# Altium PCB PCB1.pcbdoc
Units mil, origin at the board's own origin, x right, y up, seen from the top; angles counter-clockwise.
Board outline 1835 x 2230 mil, 2 copper layers (Top Layer, Bottom Layer); 38 components, 28 nets, 143 pads, 62 vias.
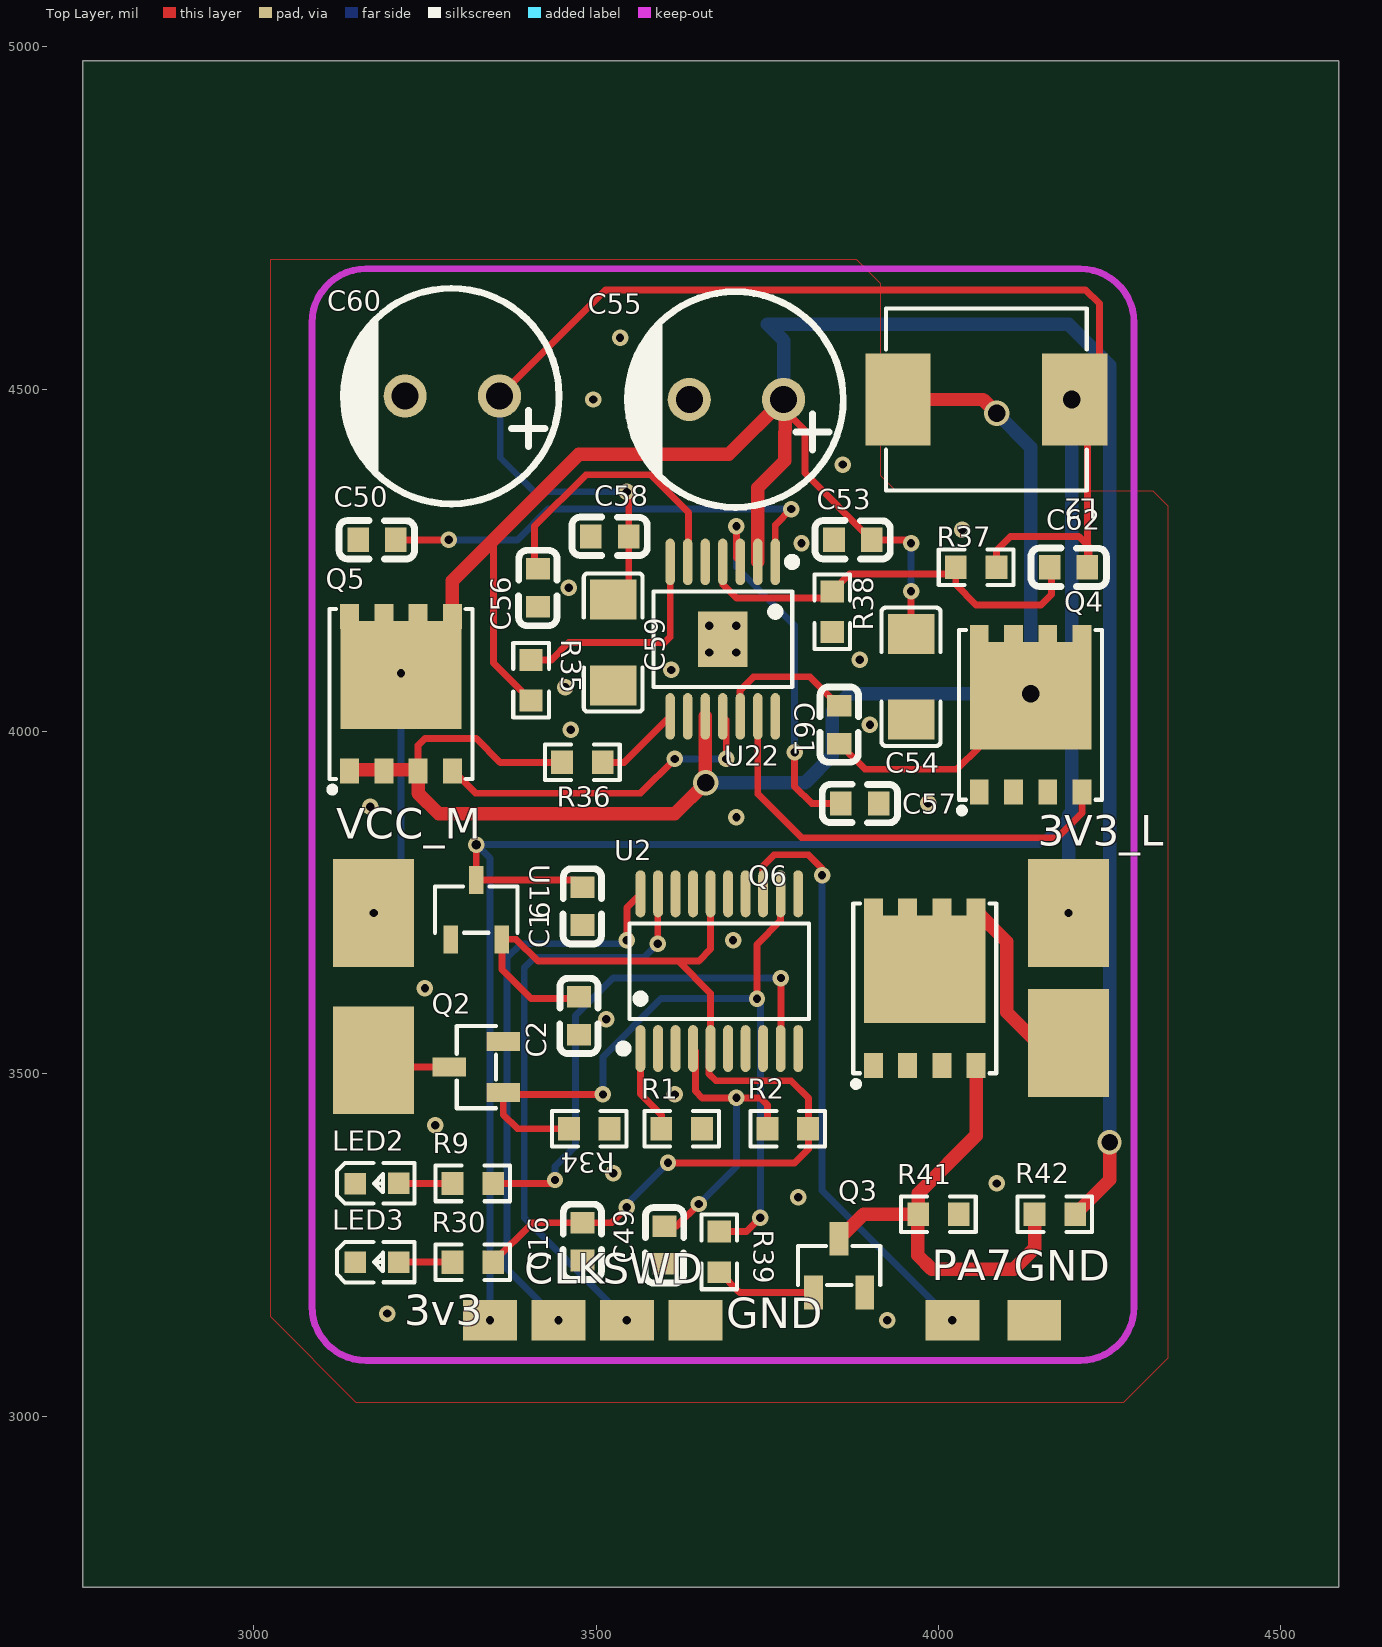
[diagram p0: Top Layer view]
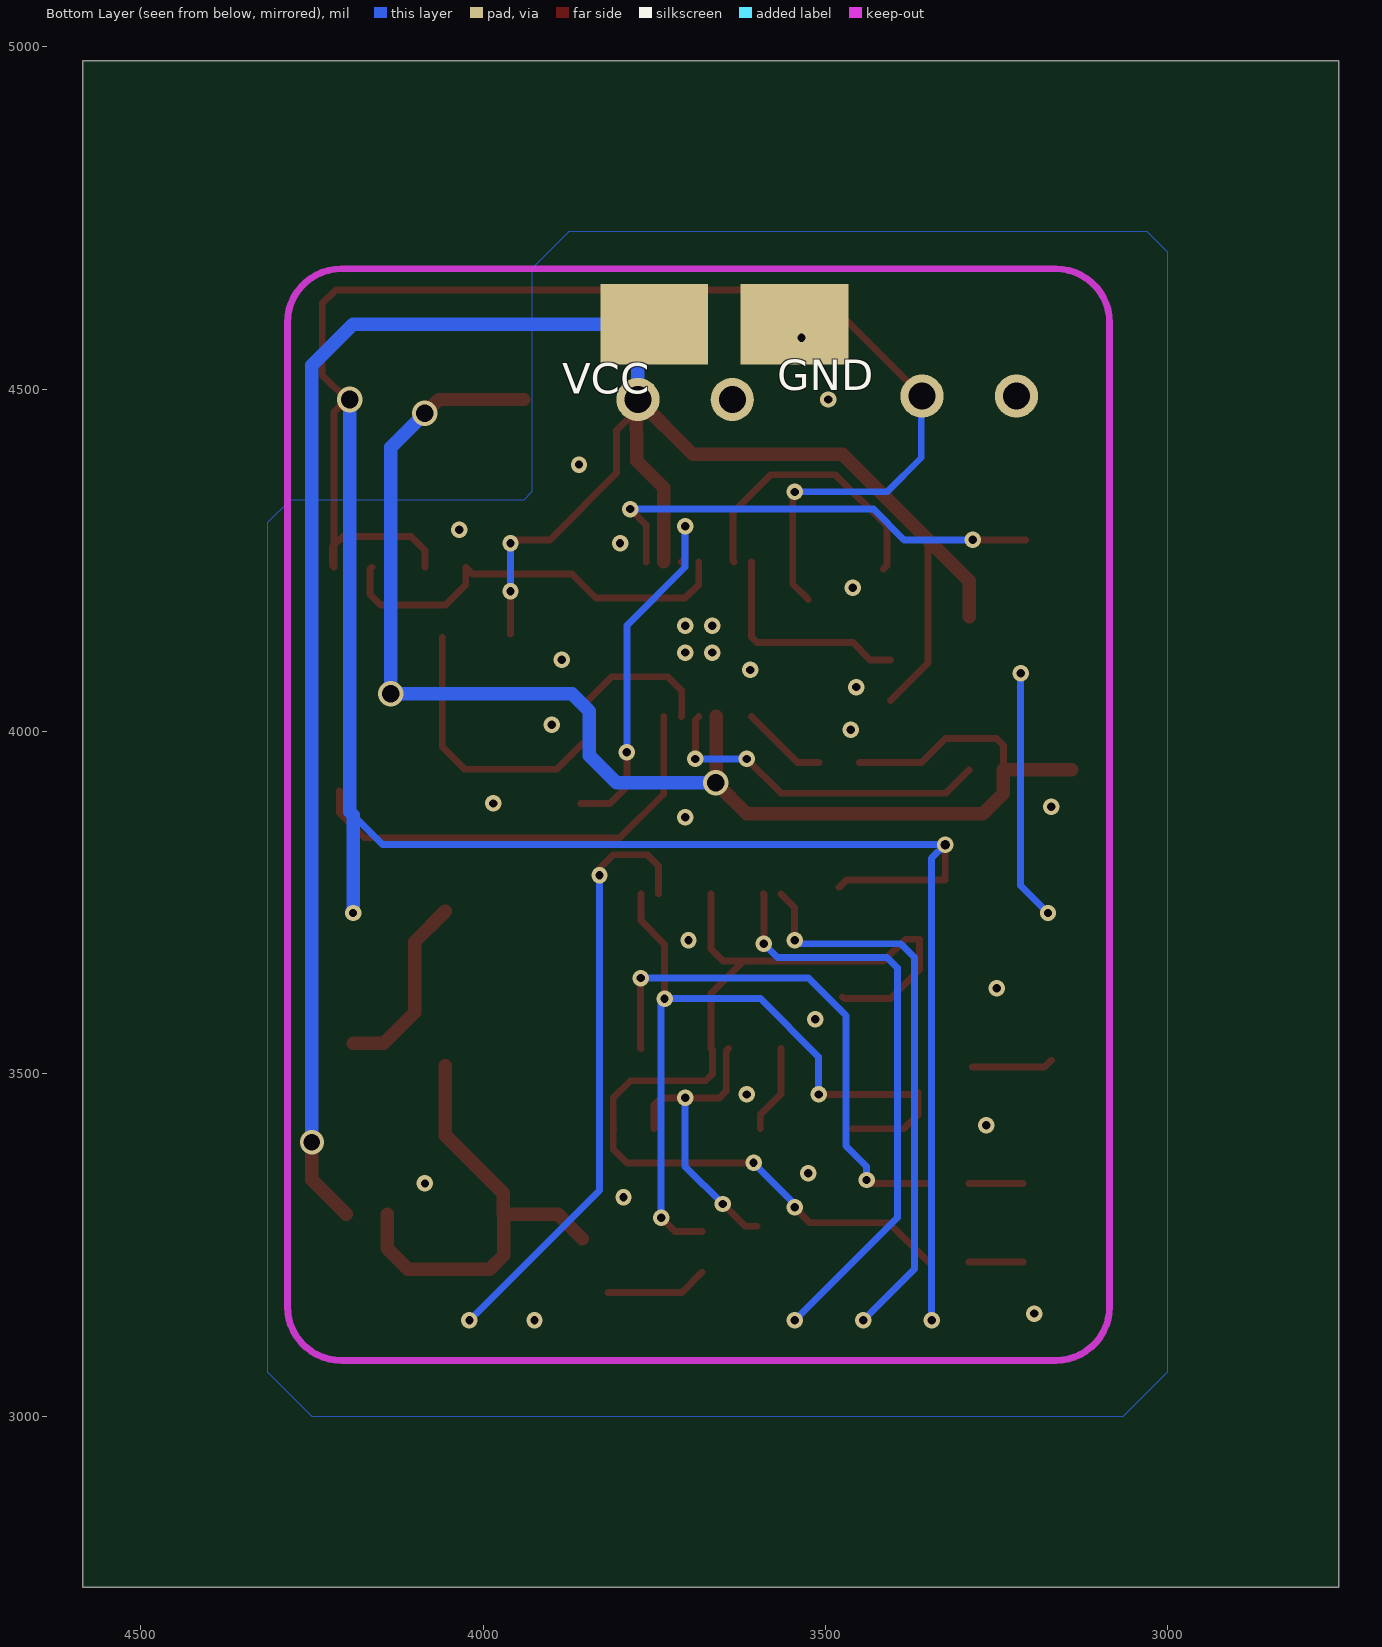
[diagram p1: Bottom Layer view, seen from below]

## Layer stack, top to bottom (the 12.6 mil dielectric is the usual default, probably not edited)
Top Layer: signal copper (thickness not stored)
Dielectric: dielectric 12.6, FR-4, Dk 4.8
Bottom Layer: signal copper (thickness not stored)

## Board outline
4585,2750 2750,2750 2750,4980 4585,4980

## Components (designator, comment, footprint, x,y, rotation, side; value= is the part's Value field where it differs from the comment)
C1 "CL10A106KP8NNNC" C0603 3480,3745 r90 top
C2 "CL10A106KP8NNNC" C0603 3475,3585 r90 top
C16 "CL10A106KP8NNNC" C0603 3480,3255 r90 top
C49 "CAP_0603" C0603 3600,3250 r90 top
C50 "CAP_0603" C0603 3180,4280 r0 top
C53 "CAP_0603" C0603 3875,4280 r0 top
C54 "CL31A106KBHNNNE" C1206 3960,4080 r90 top
C55 "KM227M035F12RR0VH2FP0" CAP-TH_BD8.0-P3.50-D0.6-FD 3705,4485 r180 top
C56 "CAP_0603" C0603 3415,4210 r90 top
C57 "CAP_0603" C0603 3885,3895 r180 top
C58 "CAP_0603" C0603 3520,4285 r0 top
C59 "CL31A106KBHNNNE" C1206 3525,4130 r90 top
C60 "KM227M035F12RR0VH2FP0" CAP-TH_BD8.0-P3.50-D0.6-FD 3290,4490 r180 top
C61 "CAP_0603" C0603 3855,4010 r270 top
C62 "CAP_0603" C0603 4190,4240 r180 top
L2 "MCS0630-100MPY1" IND-SMD_L7.3-W6.6 4070,4485 r180 top
LED2 "NCD0603R1_C84263" LED0603-RD_RED 3180,3340 r0 top
LED3 "NCD0603R1_C84263" LED0603-RD_RED 3180,3225 r0 top
Q2 "AO3400A_C347475" SOT-23-3_L2.9-W1.3-P1.90-LS2.4-BR 3325,3510 r0 top
Q3 "SS8050_C2150" SOT-23-3_L2.9-W1.3-P1.90-LS2.4-BR 3855,3220 r270 top
Q4 "BSC027N04LSG" PG-TDSON-8_L5.0-W6.0-P1.27-LS6.2-BL-EP 4134.68,4024.55 r0 top
Q5 "BSC027N04LSG" PG-TDSON-8_L5.0-W6.0-P1.27-LS6.2-BL-EP 3215,4055 r0 top
Q6 "BSC027N04LSG" PG-TDSON-8_L5.0-W6.0-P1.27-LS6.2-BL-EP 3980,3625 r0 top
R1 "0603WAF1002T5E" R0603 3625,3420 r0 top
R2 "0603WAF1002T5E" R0603 3780,3420 r0 top
R9 "0603WAF1001T5E" R0603 3320,3340 r0 top
R30 "0603WAF1001T5E" R0603 3320,3225 r0 top
R34 "Res_0603" R0603 3490,3420 r0 top
R35 "Res_0603" R0603 3405,4075 r270 top
R36 "Res_0603" R0603 3480,3955 r180 top
R37 "Res_0603" R0603 4055,4240 r0 top
R38 "Res_0603" R0603 3845,4175 r90 top
R39 "Res_0603" R0603 3680,3240 r270 top
R41 "Res_0603" R0603 4000,3295 r0 top
R42 "Res_0603" R0603 4170,3295 r0 top
U2 "STM32F030F4P6" TSSOP-20_L6.5-W4.4-P0.65-LS6.4-BL 3680,3650 r0 top
U19 "XC6206P332MR_C347376" SOT-23-3_L3.0-W1.7-P0.95-LS2.9-BR 3325,3740 r270 top
U22 "LM3150MHX/NOPB" HTSSOP-14_L5.0-W4.4-P0.65-LS6.4-BL-EP 3685,4135 r180 top

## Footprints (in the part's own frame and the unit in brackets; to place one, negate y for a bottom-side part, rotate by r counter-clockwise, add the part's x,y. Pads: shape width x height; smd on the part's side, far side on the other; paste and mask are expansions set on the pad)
C0603 [mm]
  rect 0.8x0.9 smd: 1(-0.7,0) 2(0.7,0)
  silkscreen extent -1.41,-0.71 1.39,0.72
C1206 [mm]
  rect 1.485x1.728 smd: 1(-1.593,0) 2(1.593,0)
  silkscreen extent -2.56,-1.09 2.56,1.09
CAP-TH_BD8.0-P3.50-D0.6-FD [mm]
  round 1.6 hole 1: 1(-1.75,0) 2(1.75,0)
  silkscreen extent -3.96,-4 4.04,4
HTSSOP-14_L5.0-W4.4-P0.65-LS6.4-BL-EP [mm]
  oval 0.343x1.731 smd: 1(-1.95,-2.866) 2(-1.3,-2.866) 3(-0.65,-2.866) 4(0,-2.866) 5(0.65,-2.866) 6(1.3,-2.866) 7(1.95,-2.866) 8(1.95,2.866) 9(1.3,2.866) 10(0.65,2.866) 11(0,2.866) 12(-0.65,2.866) 13(-1.3,2.866) 14(-1.95,2.866)
  rect 1.83x2.055 smd: 15(0,0)
  silkscreen extent -2.72,-3.02 2.58,1.77
IND-SMD_L7.3-W6.6 [mm]
  rect 2.424x3.42 smd: 1(3.278,0) 2(-3.278,0)
  silkscreen extent -3.73,-3.38 3.73,3.38
LED0603-RD_RED [mm]
  rect 0.8x0.8 smd: 1(-0.8,-0.003) 2(0.8,0.003)
  silkscreen extent -1.49,-0.75 1.39,0.76
PG-TDSON-8_L5.0-W6.0-P1.27-LS6.2-BL-EP [mm]
  rect 0.7x0.925 smd: 1(-1.905,-2.865) 2(-0.635,-2.865) 3(0.635,-2.865) 4(1.905,-2.865) 5(1.905,2.865) 6(0.635,2.865) 7(-0.635,2.865) 8(-1.905,2.865)
  rect 4.5x4 smd: 9(0,0.705)
  silkscreen extent -2.66,-3.66 2.65,3.15
R0603 [mil]
  rect 31.75x34.02 smd: 1(-29.66,0) 2(29.66,0)
  silkscreen extent -55,-26 55,26
SOT-23-3_L2.9-W1.3-P1.90-LS2.4-BR [mm]
  rect 1.25x0.7 smd: 1(1,-0.95) 2(1,0.95) 3(-1,0)
  silkscreen extent -0.73,-1.53 0.73,1.53
SOT-23-3_L3.0-W1.7-P0.95-LS2.9-BR [mil]
  rect 40.85x20.95 smd: 1(43.36,-37.4) 2(43.36,37.4) 3(-43.36,0)
  silkscreen extent -34,-60 34,60
TSSOP-20_L6.5-W4.4-P0.65-LS6.4-BL [mil]
  oval 14.33x68.58 smd: 1(-115.16,-113.03) 2(-89.57,-113.03) 3(-63.98,-113.03) 4(-38.39,-113.03) 5(-12.79,-113.03) 6(12.8,-113.03) 7(38.39,-113.03) 8(63.98,-113.03) 9(89.57,-113.03) 10(115.16,-113.03) 11(115.16,113.03) 12(89.57,113.03) 13(63.98,113.03) 14(38.39,113.03) 15(12.8,113.03) 16(-12.79,113.03) 17(-38.39,113.03) 18(-63.98,113.03) 19(-89.57,113.03) 20(-115.16,113.03)
  silkscreen extent -146,-119 131,70

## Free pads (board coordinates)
  rect 118.11x157.48 smd: 21(3175,3520) 21(3175,3735) 21(4190,3545) 21(4190,3735)
  rect 78.74x59.06 smd: 21(3345,3140) 21(3445,3140) 21(3545,3140) 21(3645,3140) 21(4020.79,3140) 21(4140,3140)
  rect 157.48x118.11 smd far side: 21(3545,4595) 21(3750,4595)

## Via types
v1: diameter 24.02, hole 12.2, Top Layer to Bottom Layer, 52 vias
v2: diameter 37.4, hole 25.59, Top Layer to Bottom Layer, 4 vias
v3: diameter 24, hole 12, Top Layer to Bottom Layer, 4 vias
v4: diameter 24.02, hole 13.78, Top Layer to Bottom Layer, 1 vias
v5: diameter 35.43, hole 24.02, Top Layer to Bottom Layer, 1 vias

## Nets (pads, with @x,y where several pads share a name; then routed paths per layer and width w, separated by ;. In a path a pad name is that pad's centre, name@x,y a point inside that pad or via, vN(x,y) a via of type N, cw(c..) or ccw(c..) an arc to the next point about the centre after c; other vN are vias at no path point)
3V: C2.2 C16.2 R2.2 R30.2 U2.5 U2.16 U19.2 | length 1533.1
  Top Layer w10: R30.2 3407.22,3282.56 C16.2 3522.56,3282.56 v1(3545,3305) ; C2.2 3472.44,3610 3405,3610 3362.4,3652.6 U19.2 3383.36,3696.64 3415,3665 3620,3665 ; v1(3605,3370) 3790,3370 3810,3390 3810,3419.66 R2.2 3810,3420.34 3810,3465 3785,3490 3675,3490 3665,3500 3665,3534.76 U2.5 3667.21,3617.79 3620,3665 ; U2.16 3667.21,3682.21 3650,3665 3620,3665
  Bottom Layer w10: v1(3545,3305) 3545,3310 v1(3605,3370)
3V3: C1.2 C58.2 C59.2 C60.1 C62.1 L2.2 pad.21@3345,3140 pad.21@4190,3735 R37.2 U19.3 | length 4574.9
  Top Layer w9.65: C59.2 3547.56,4215.26 C58.2 3547.56,4347.44 v1(3545,4350)
  Top Layer w10: v4(3325,3835) U19.3 3469.2,3783.36 C1.2 ; C60.1 3513.9,4645 4215,4645 4235,4625 4235,4520.94 L2.2 4217.56,4466.5 4217.56,4272.44 ; R37.2 4084.66,4264.66 4105,4285 4205,4285 4217.56,4272.44 ; 4217.56,4272.44 C62.1 4220,4242.44 4220,4270 4217.56,4272.44
  Bottom Layer w9.65: C60.1 3360,4488.9 3360,4400 3410,4350 v1(3545,4350)
  Bottom Layer w10: v1(3345,3140) 3345,3815 v4(3325,3835) 4147.01,3835 4190,3877.99
  Bottom Layer w19.68: v1(4190,3735) 4190,3877.99 4195,3882.99 v2(4195,4485)
$1N3902: R1.1 U2.1 | length 129.6
  Top Layer w10: U2.1 3564.84,3470.5 3595.34,3440 R1.1
$1N3919: LED2.2 R9.1 | length 78.9
  Top Layer w10: LED2.2 3211.61,3340 R9.1
$1N3958: LED3.2 R30.1 | length 78.9
  Top Layer w10: LED3.2 3290.2,3225.14 R30.1
$1N3965: C49.2 R2.1 U2.4 | length 453
  Top Layer w10: C49.2 3617.56,3277.56 v1(3650,3310) ; U2.4 3645,3533.58 3645,3475 3655,3465 v1(3705,3465) 3740,3465 3750.34,3454.66 R2.1
  Bottom Layer w10: v1(3650,3310) 3705,3365 v1(3705,3465)
$1N4069: C50.2 U22.1 | length 682.9
  Top Layer w10: C50.2 v1(3285,4280) ; U22.1 3761.77,4301.77 v1(3785,4325)
  Bottom Layer w10: v1(3285,4280) 3385,4280 3430,4325 v1(3785,4325)
$1N4674: R35.1 U22.7 | length 326.7
  Top Layer w10: R35.1 3434.66,4104.66 3460,4130 3600,4130 3608.23,4138.23 U22.7
$1N4765: C56.2 U22.6 | length 416
  Top Layer w10: C56.2 3410,4242.56 3410,4300 3485,4375 3580,4375 3635,4320 3635,4249.01 U22.6
$1N4847: C57.2 U22.3 | length 547.5
  Top Layer w10: v1(3705,4300) 3705,4253.41 U22.3 ; v1(3790,3970) 3790,3920 3815,3895 C57.2
  Bottom Layer w10: v1(3705,4300) 3705,4240 3790,4155 v1(3790,3970)
$1N5111: R36.1 U22.8 | length 126.4
  Top Layer w10: R36.1 3541.05,3955 U22.8
$1N5322: Q5.4 U22.11 | length 499
  Top Layer w10: Q5.4@3290,3944 3324,3910 3565,3910 v1(3615,3960) ; U22.11 3690,4017.18 v1(3690,3960)
  Bottom Layer w10: v1(3615,3960) v1(3690,3960)
$1N5328: Q4.4 U22.13 | length 660.7
  Top Layer w10: U22.13 3736.18,3908.82 3800,3845 4173.63,3845 4209.68,3881.05 Q4.4@4209.68,3913.55
$1N5815: C61.1 U22.12 | length 208.9
  Top Layer w10: U22.12 3710,4022.76 3710,4060 3730,4080 3812.56,4080 C61.1
$1N6183: C62.2 R37.1 R38.2 U22.4 | length 624.6
  Top Layer w10: U22.4 3685,4215 3705,4195 3835.34,4195 R38.2 3870.34,4230 4015.34,4230 R37.1 4025.34,4214.66 4055,4185 4150,4185 4165,4200 4165,4237.44 C62.2
$1N15337: C61.2 L2.1 Q4.5 Q4.6 Q4.7 Q4.8 Q4.9 Q5.1 Q5.2 Q5.3 R36.2 U22.10 | length 2491.1
  Top Layer w10: Q5.3@3240,3944 3240,3980 3250,3990 3325,3990 3360,3955 R36.2 ; C61.2 3892.44,3945 4027.37,3945 4059.68,3977.3 Q4.8
  Top Layer w19.68: Q5.1@3140,3944 3240,3944 3240,3910 3270,3880 3615,3880 v2(3660,3925) 3659.41,3925.59 U22.10 ; L2.1 4065,4485 v2(4085,4465)
  Bottom Layer w19.68: v2(3660,3925) 3805,3925 3845,3965 3845,4030 3870,4055 v2(4135,4055) 4135,4415 v2(4085,4465)
$1N15416: Q3.1 R39.2 | length 149.9
  Top Layer w10: R39.2 3709.71,3180.63 Q3.1
$1N18673: Q3.3 Q6.4 R41.1 R42.1 | length 683.4
  Top Layer w19.68: Q3.3 3890.63,3295 R41.1 ; Q6.4 4055,3410 3970.34,3325.34 R41.1 ; R42.1 4140.34,3245.34 4110,3215 3990,3215 3970,3235 3970,3294.66 R41.1
GND: C1.1 C2.1 C16.1 C49.1 C50.1 C53.1 C54.1 C55.2 C56.1 C57.1 C58.1 C59.1 C60.2 LED2.1 LED3.1 pad.21@3545,4595 pad.21@3645,3140 pad.21@4140,3140 Q2.2 Q3.2 Q4.1 Q4.2 Q4.3 Q6.1 Q6.2 Q6.3 R1.2 R34.2 R38.1 R41.2 U2.15 U19.1 U22.5 U22.9 U22.14
  other v1: 3925,3140 3195,3150 3795,3320 4085,3340 3525,3355 3265,3425 3615,3470 3515,3580 3250,3625 3700,3695 3705,3875 3170,3890 3985,3895 3463.22,4002.88 3900,4010 3455,4065 3610,4090 3885,4105 3460,4210 3800,4275 4035,4295 3860,4390 3495.93,4484.97 3535,4575
LED_GND: pad.21@4190,3545 Q6.5 Q6.6 Q6.7 Q6.8 Q6.9 | length 275.1
  Top Layer w19.68: Q6.5 4100,3692.8 4100,3590 4145,3545 pad.21@4190,3545
MOTOR_GND: pad.21@3175,3520 Q2.3 | length 119.8
  Top Layer w10: pad.21@3170,3520 3180,3510 Q2.3
PA3: R9.2 U2.9 | length 770.8
  Top Layer w10: R9.2 3435,3340 v1(3440,3345) ; U2.9 3770,3537.4 v1(3770,3640)
  Bottom Layer w10: v1(3440,3345) 3440,3365 3470,3395 3470,3585 3525,3640 v1(3770,3640)
PA6: Q2.1 R34.1 R39.1 U2.12 | length 1156.2
  Top Layer w10: R34.1 3385,3420 3364.37,3440.63 Q2.1 3366.97,3470 v1(3510,3470) ; R39.1 3719.66,3269.66 v1(3740,3290) ; v1(3735,3610) 3735,3689.17 3769.57,3723.74 U2.12
  Bottom Layer w10: v1(3510,3470) 3510,3525 3595,3610 v1(3735,3610) 3740,3605 v1(3740,3290)
PA7: pad.21@4020.79,3140 U2.13 | length 880.6
  Top Layer w10: U2.13 3743.98,3803.98 3760,3820 3810,3820 3830,3800 v1(3830,3790)
  Bottom Layer w10: v1(3830,3790) 3830,3330 v1(4020,3140)
SWCLK: pad.21@3445,3140 U2.20 | length 822.7
  Top Layer w10: v1(3545,3695) 3545,3743.19 U2.20
  Bottom Layer w10: v1(3445,3140) 3370,3215 3370,3670 3390,3690 3540,3690 v1(3545,3695)
SWDIO: pad.21@3545,3140 U2.19 | length 859.8
  Top Layer w10: v1(3590,3690) 3590,3762.6 U2.19
  Bottom Layer w10: v1(3545,3140) 3395,3290 3395,3655 3410,3670 3570,3670 v1(3590,3690)
VCC: C53.2 C54.2 C55.1 pad.21@3175,3735 pad.21@3750,4595 Q5.5 Q5.6 Q5.7 Q5.8 Q5.9 R35.2 R42.2 U22.2 | length 3876.9
  Top Layer w10: 3350.25,4280.25 3350.25,4100.09 R35.2 ; C55.1@3776.18,4482.72 3776.18,4468.82 3805,4440 3805,4377.56 C53.2 3955,4280 v1(3960,4275) ; C54.2 v1(3960,4205)
  Top Layer w19.68: Q5.5 3290,4220 3350.25,4280.25 3475,4405 3693.9,4405 C55.1 3776.18,4482.72 3775.42,4395.42 3736.18,4356.18 U22.2 ; R42.2 4250,3345.34 v5(4250,3400)
  Bottom Layer w10: v1(3175,3735) 3215,3775 v1(3215,4085) ; v1(3960,4205) v1(3960,4275)
  Bottom Layer w19.68: C55.1 3773.9,4571.1 3750,4595 4190,4595 4250,4535 v5(4250,3400)
"": U2.2 U2.3 U2.6 U2.7 U2.8 U2.10 U2.11 U2.14 U2.17 U2.18 U22.15
  other v3: 3665.31,4115.31 3704.68,4115.31 3665.31,4154.69 3704.68,4154.69

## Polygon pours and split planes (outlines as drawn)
GND on Top Layer (solid, remove dead copper, pour order 0): 3025,4690 3880,4690 3915,4655 3915,4374.53 3937.45,4352.08 4312.92,4352.08 4335,4330 4335,3085 4270,3020 3150,3020 3025,3145
GND on Bottom Layer (solid, remove dead copper, pour order 1): 3030,4730 3874.88,4730 3928.95,4675.93 3928.95,4349.93 3940.94,4337.94 4282.06,4337.94 4315,4305 4315,3065 4250,3000 3065,3000 3000,3065 3000,4700

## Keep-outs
Board Outline Layer:
  lines w10 net "": 3085,3160.18 ccw(c3163.74,3160.18) 3163.74,3081.44 4207.05,3081.44 ccw(c4207.05,3160.18) 4285.79,3160.18 4285.79,4597.19 ccw(c4207.05,4597.19) 4207.05,4675.93 3163.74,4675.93 ccw(c3163.74,4597.19) 3085,4597.19 3085,3160.18

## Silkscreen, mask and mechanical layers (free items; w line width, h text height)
Top Silkscreen Layer:
  text "VCC_M" at 3120.27,3843.23 h44.6
  text "3V3_L" at 4145.27,3833.23 h44.6
  text "PA7" at 3990.52,3198.54 h44.6
  text "GND" at 4110.05,3198.23 h44.6
  text "CLK" at 3395.05,3193.23 h44.6
  text "SWD" at 3510.05,3193.23 h44.6
  text "3v3" at 3220.05,3133.23 h44.6
  text "GND" at 3690.05,3128.23 h44.6
Bottom Silkscreen Layer:
  text "GND" at 3570.05,4498.23 h44.6
  text "VCC" at 3884.58,4493.54 h44.6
